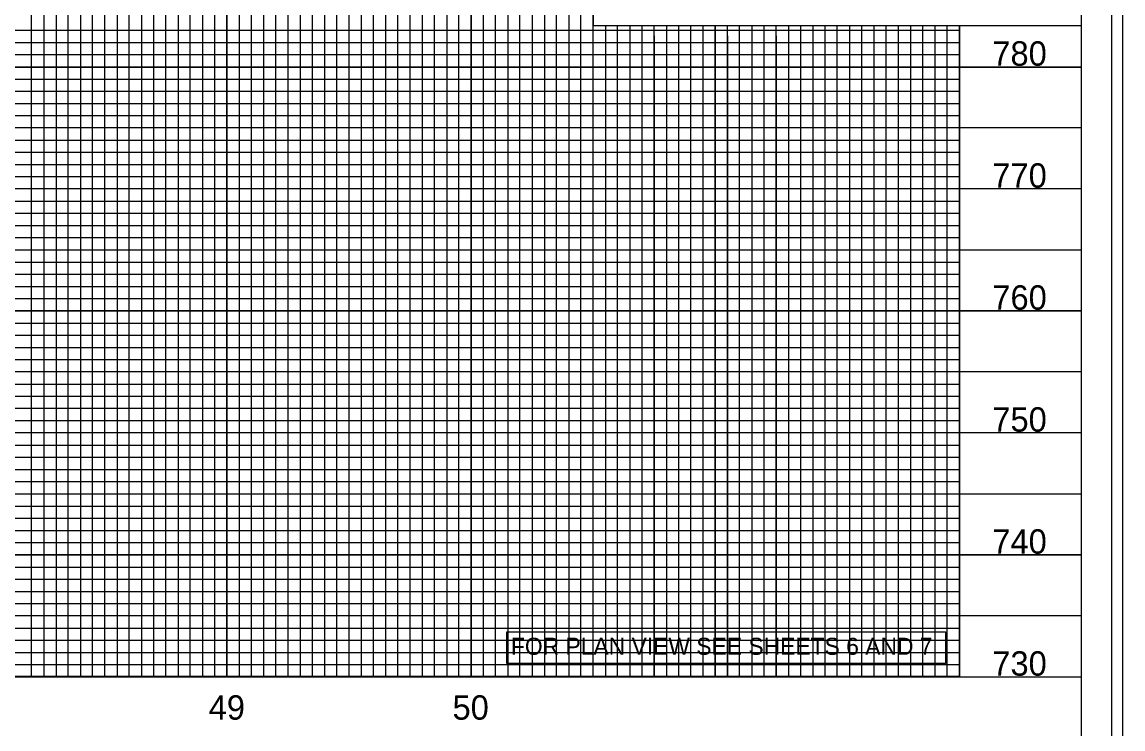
# Model space of a CAD drawing. Extents: x 1755181 to 1757273, y 729911 to 735411.
# Drawn here: x 1756413.7 to 1756864.7, y 733764.5 to 734054.2 of the extents above; entities that cross this region are included whole.
import ezdxf

# ---------------------------------------------------------------- set-up
doc = ezdxf.new("R2010")
doc.units = 0
for name, color, linetype in [('Exist Vertical Profile Horizontal Axis Label Major', 7, 'Continuous'), ('Exist Vertical Profile Vertical Axis Label', 7, 'Continuous'), ('Old_Level_43', 7, 'Continuous'), ('Prop Grid Mask', 7, 'Continuous'), ('Prop VPI Label', 7, 'Continuous'), ('Scratch_Level_3', 7, 'Continuous'), ('Sheet DOT Grid CELL', 7, 'Continuous'), ('Sheet Plot Border Inside CELL', 7, 'Continuous'), ('Sheet Plot Border Outside CELL', 7, 'Continuous'), ('Sheet Profile CELL', 7, 'Continuous'), ('Sheet Profile Grid Major CELL', 7, 'Continuous'), ('Sheet Profile Grid Middle CELL', 7, 'Continuous'), ('Sheet Profile Grid Minor CELL', 7, 'Continuous')]:
    doc.layers.add(name, color=color, linetype=linetype)

msp = doc.modelspace()

# ---------------------------------------------------------------- linework, layer by layer
at = {"layer": 'Old_Level_43'}
msp.add_lwpolyline([(1756847.68, 734052.66), (1756647.63, 734052.66), (1756647.63, 734089.43)], dxfattribs=at)
at = {"layer": 'Prop Grid Mask'}
msp.add_lwpolyline([(1756612.34, 733804.29), (1756792.01, 733804.29), (1756792.01, 733791.28), (1756612.34, 733791.28)], close=True, dxfattribs=at)
at = {"layer": 'Scratch_Level_3'}
msp.add_lwpolyline([(1755397.67, 733785.92), (1755397.67, 734285.78), (1756647.65, 734285.78), (1756647.63, 734052.8), (1756797.72, 734052.78), (1756797.72, 733785.92)], close=True, dxfattribs=at)
at = {"layer": 'Sheet DOT Grid CELL'}
for p, q in [((1756447.67, 733785.78), (1756447.67, 734285.78)), ((1756497.67, 733785.78), (1756497.67, 734285.78)), ((1756547.67, 733785.78), (1756547.67, 734285.78)), ((1756597.67, 733785.78), (1756597.67, 734285.78)), ((1756647.67, 733785.78), (1756647.67, 734148.23)), ((1756697.67, 733785.78), (1756697.67, 734052.66)), ((1756747.67, 733785.78), (1756747.67, 734052.66)), ((1756797.67, 733785.78), (1756797.67, 734052.66)), ((1756847.67, 734035.78), (1755347.67, 734035.78)), ((1756847.67, 733985.78), (1755347.67, 733985.78)), ((1756847.67, 733935.78), (1755347.67, 733935.78)), ((1756847.67, 733885.78), (1755347.67, 733885.78)), ((1756847.67, 733835.78), (1755347.67, 733835.78))]:
    msp.add_line(p, q, dxfattribs=at)
at = {"layer": 'Sheet Plot Border Inside CELL'}
msp.add_lwpolyline([(1755193.67, 733233.23), (1756860.17, 733233.23), (1756860.17, 734288.33), (1755193.67, 734288.33)], close=True, dxfattribs=at)
at = {"layer": 'Sheet Plot Border Outside CELL'}
msp.add_lwpolyline([(1755180.67, 733210.78), (1756864.67, 733210.78), (1756864.67, 734310.78), (1755180.67, 734310.78)], close=True, dxfattribs=at)
at = {"layer": 'Sheet Profile CELL'}
msp.add_line((1755347.67, 733785.78), (1756847.67, 733785.78), dxfattribs=at)
msp.add_lwpolyline([(1756847.67, 734285.78), (1755347.67, 734285.78), (1755347.67, 733235.78), (1756847.67, 733235.78)], close=True, dxfattribs=at)
at = {"layer": 'Sheet Profile Grid Major CELL'}
for points in [[(1756397.67, 733785.78), (1756447.67, 733785.78), (1756447.67, 734285.78), (1756497.67, 734285.78), (1756497.67, 733785.78), (1756547.67, 733785.78), (1756547.67, 734285.78), (1756597.67, 734285.78), (1756597.67, 733785.78), (1756647.67, 733785.78), (1756647.67, 734285.78), (1756673.97, 734285.78)], [(1756797.67, 734052.66), (1756797.67, 733785.78), (1756847.67, 733785.78), (1756847.67, 734135.78)], [(1756647.63, 734085.78), (1755347.67, 734085.78), (1755347.67, 734035.78), (1756847.67, 734035.78)], [(1756697.67, 734052.66), (1756697.67, 733785.78), (1756747.67, 733785.78), (1756747.67, 733785.78), (1756747.67, 734052.66)], [(1756847.67, 733985.78), (1755347.67, 733985.78), (1755347.67, 733935.78), (1756847.67, 733935.78)], [(1756847.67, 733885.78), (1755347.67, 733885.78), (1755347.67, 733885.78), (1755347.67, 733835.78), (1756847.67, 733835.78)]]:
    msp.add_lwpolyline(points, dxfattribs=at)
at = {"layer": 'Sheet Profile Grid Middle CELL'}
for points in [[(1756372.67, 734285.78), (1756422.67, 734285.78), (1756422.67, 733785.78), (1756472.67, 733785.78), (1756472.67, 734285.78), (1756522.67, 734285.78), (1756522.67, 733785.78), (1756572.67, 733785.78), (1756572.67, 734285.78), (1756622.67, 734285.78), (1756622.67, 733785.78), (1756672.67, 733785.78), (1756672.67, 734052.66)], [(1756672.67, 734048.58), (1756672.67, 733785.78), (1756722.67, 733785.78), (1756722.67, 734052.66)], [(1756722.67, 734048.58), (1756722.67, 733785.78), (1756772.67, 733785.78), (1756772.67, 734052.66)], [(1756847.67, 734010.78), (1755347.67, 734010.78), (1755347.67, 733960.78), (1756847.67, 733960.78)], [(1756847.67, 733910.78), (1755347.67, 733910.78), (1755347.67, 733860.78), (1756847.67, 733860.78)], [(1756847.67, 733810.78), (1755347.67, 733810.78)]]:
    msp.add_lwpolyline(points, dxfattribs=at)
at = {"layer": 'Sheet Profile Grid Minor CELL'}
for p, q in [((1756797.67, 734050.78), (1755397.67, 734050.78)), ((1755397.67, 734045.78), (1756797.67, 734045.78)), ((1756797.67, 734040.78), (1755397.67, 734040.78)), ((1755397.67, 734030.78), (1756797.67, 734030.78)), ((1756797.67, 734025.78), (1755397.67, 734025.78)), ((1755397.67, 734020.78), (1756797.67, 734020.78)), ((1756797.67, 734015.78), (1755397.67, 734015.78)), ((1755397.67, 734005.78), (1756797.67, 734005.78)), ((1756797.67, 734000.78), (1755397.67, 734000.78)), ((1755397.67, 733995.78), (1756797.67, 733995.78)), ((1756797.67, 733990.78), (1755397.67, 733990.78)), ((1755397.67, 733980.78), (1756797.67, 733980.78)), ((1756797.67, 733975.78), (1755397.67, 733975.78)), ((1755397.67, 733970.78), (1756797.67, 733970.78)), ((1756797.67, 733965.78), (1755397.67, 733965.78)), ((1755397.67, 733955.78), (1756797.67, 733955.78)), ((1756797.67, 733950.78), (1755397.67, 733950.78)), ((1755397.67, 733945.78), (1756797.67, 733945.78)), ((1756797.67, 733940.78), (1755397.67, 733940.78)), ((1755397.67, 733930.78), (1756797.67, 733930.78)), ((1756797.67, 733925.78), (1755397.67, 733925.78)), ((1755397.67, 733920.78), (1756797.67, 733920.78)), ((1756797.67, 733915.78), (1755397.67, 733915.78)), ((1755397.67, 733905.78), (1756797.67, 733905.78)), ((1756797.67, 733900.78), (1755397.67, 733900.78)), ((1756797.67, 733895.78), (1755397.67, 733895.78)), ((1756797.67, 733890.78), (1755397.67, 733890.78)), ((1755397.67, 733880.78), (1756797.67, 733880.78)), ((1756797.67, 733875.78), (1755397.67, 733875.78)), ((1755397.67, 733870.78), (1756797.67, 733870.78)), ((1756797.67, 733865.78), (1755397.67, 733865.78)), ((1755397.67, 733855.78), (1756797.67, 733855.78)), ((1756797.67, 733850.78), (1755397.67, 733850.78)), ((1755397.67, 733845.78), (1756797.67, 733845.78)), ((1756797.67, 733840.78), (1755397.67, 733840.78)), ((1755397.67, 733830.78), (1756797.67, 733830.78)), ((1756797.67, 733825.78), (1755397.67, 733825.78)), ((1755397.67, 733820.78), (1756797.67, 733820.78)), ((1756797.67, 733815.78), (1755397.67, 733815.78)), ((1755397.67, 733805.78), (1756797.67, 733805.78)), ((1756797.67, 733800.78), (1755397.67, 733800.78)), ((1755397.67, 733795.78), (1756797.67, 733795.78)), ((1756797.67, 733790.78), (1756797.67, 733790.78))]:
    msp.add_line(p, q, dxfattribs=at)
for points in [[(1756412.67, 733785.78), (1756417.67, 733785.78), (1756417.67, 734285.78)], [(1756427.67, 734285.78), (1756427.67, 733785.78), (1756432.67, 733785.78), (1756432.67, 734285.78)], [(1756437.67, 734285.78), (1756437.67, 733785.78), (1756442.67, 733785.78), (1756442.67, 734285.78)], [(1756452.67, 734285.78), (1756452.67, 733785.78), (1756457.67, 733785.78), (1756457.67, 734285.78)], [(1756462.67, 734285.78), (1756462.67, 733785.78), (1756467.67, 733785.78), (1756467.67, 734285.78)], [(1756477.67, 734285.78), (1756477.67, 733785.78), (1756482.67, 733785.78), (1756482.67, 734285.78)], [(1756487.67, 734285.78), (1756487.67, 733785.78), (1756492.67, 733785.78), (1756492.67, 734285.78)], [(1756502.67, 734285.78), (1756502.67, 733785.78), (1756507.67, 733785.78), (1756507.67, 734285.78)], [(1756512.67, 734285.78), (1756512.67, 733785.78), (1756517.67, 733785.78), (1756517.67, 734285.78)], [(1756527.67, 734285.78), (1756527.67, 733785.78), (1756532.67, 733785.78), (1756532.67, 734285.78)], [(1756537.67, 734285.78), (1756537.67, 733785.78)], [(1756537.67, 733785.78), (1756542.67, 733785.78), (1756542.67, 734285.78)], [(1756552.67, 734285.78), (1756552.67, 733785.78), (1756557.67, 733785.78), (1756557.67, 734285.78)], [(1756562.67, 734285.78), (1756562.67, 733785.78), (1756567.67, 733785.78), (1756567.67, 734285.78)], [(1756577.67, 734285.78), (1756577.67, 733785.78), (1756582.67, 733785.78), (1756582.67, 734285.78)], [(1756587.67, 734285.78), (1756587.67, 733785.78), (1756592.67, 733785.78), (1756592.67, 734285.78)], [(1756602.67, 734285.78), (1756602.67, 733785.78), (1756607.67, 733785.78), (1756607.67, 734285.78)], [(1756612.67, 734285.78), (1756612.67, 733785.78), (1756617.67, 733785.78), (1756617.67, 734285.78)], [(1756627.67, 734285.78), (1756627.67, 733785.78), (1756632.67, 733785.78), (1756632.67, 734285.78)], [(1756637.67, 734285.78), (1756637.67, 733785.78), (1756642.67, 733785.78), (1756642.67, 734285.78)], [(1756652.67, 734052.66), (1756652.67, 733785.78), (1756657.67, 733785.78), (1756657.67, 734052.66)], [(1756662.67, 734052.66), (1756662.67, 733785.78), (1756667.67, 733785.78), (1756667.67, 734052.66)], [(1756677.67, 734052.66), (1756677.67, 733785.78), (1756677.67, 733785.78), (1756682.67, 733785.78), (1756687.67, 733785.78), (1756687.67, 734052.66)], [(1756682.67, 734052.66), (1756682.67, 733785.78)], [(1756692.64, 734052.66), (1756692.57, 733785.83), (1756697.57, 733785.83), (1756702.67, 733785.78), (1756702.67, 734052.66)], [(1756702.67, 734048.58), (1756702.67, 733785.78), (1756707.67, 733785.78), (1756707.67, 734052.66)], [(1756712.67, 734052.66), (1756712.67, 733785.78), (1756717.67, 733785.78), (1756717.67, 734052.66)], [(1756727.67, 734052.66), (1756727.67, 733785.78), (1756732.67, 733785.78), (1756732.67, 734052.66)], [(1756737.67, 734052.66), (1756737.67, 733785.78), (1756742.67, 733785.78), (1756742.67, 734052.66)], [(1756752.67, 734052.66), (1756752.67, 733785.78), (1756757.67, 733785.78), (1756757.67, 734052.66)], [(1756762.67, 734052.66), (1756762.67, 733785.78), (1756767.67, 733785.78), (1756767.67, 734052.66)], [(1756777.67, 734052.66), (1756777.67, 733785.78), (1756782.67, 733785.78), (1756782.67, 734052.66)], [(1756787.67, 734052.66), (1756787.67, 733785.78), (1756792.67, 733785.78), (1756792.67, 734052.66)], [(1756797.67, 733790.78), (1755397.67, 733790.78)]]:
    msp.add_lwpolyline(points, dxfattribs=at)

# ---------------------------------------------------------------- texts
at = {"layer": 'Exist Vertical Profile Horizontal Axis Label Major'}
for s, p in [('49', (1756490.18, 733768.28)), ('50', (1756590.06, 733768.28))]:
    msp.add_text(s, height=10, dxfattribs=at).set_placement(p)
at = {"layer": 'Exist Vertical Profile Vertical Axis Label'}
for s, p in [('780', (1756811.15, 734036.31)), ('770', (1756811.15, 733986.31)), ('760', (1756811.15, 733936.31)), ('750', (1756811.15, 733886.31)), ('740', (1756811.15, 733836.31)), ('730', (1756811.15, 733786.31))]:
    msp.add_text(s, height=10, dxfattribs=at).set_placement(p)
at = {"layer": 'Prop VPI Label'}
msp.add_text('FOR PLAN VIEW SEE SHEETS 6 AND 7', height=7, dxfattribs=at).set_placement((1756613.98, 733794.86))

doc.saveas('drawing.dxf')
